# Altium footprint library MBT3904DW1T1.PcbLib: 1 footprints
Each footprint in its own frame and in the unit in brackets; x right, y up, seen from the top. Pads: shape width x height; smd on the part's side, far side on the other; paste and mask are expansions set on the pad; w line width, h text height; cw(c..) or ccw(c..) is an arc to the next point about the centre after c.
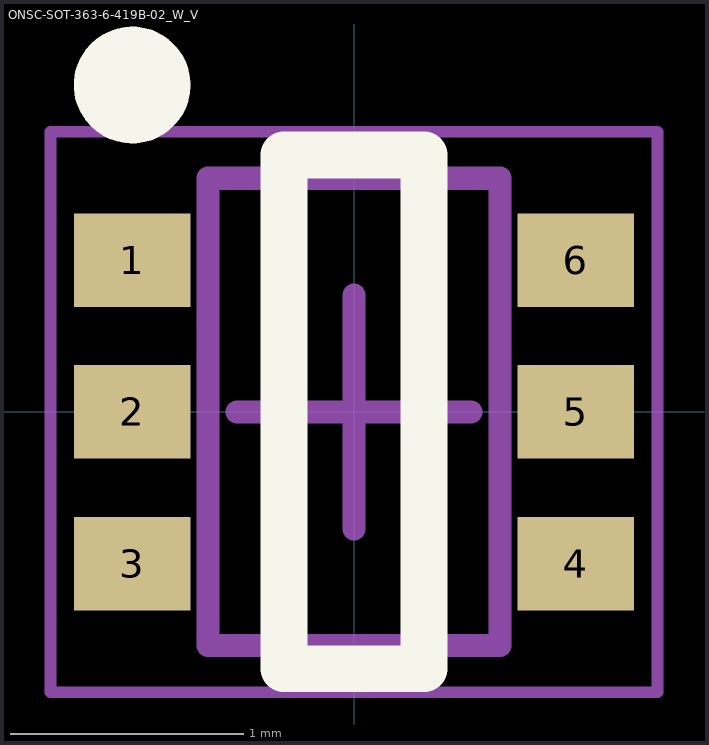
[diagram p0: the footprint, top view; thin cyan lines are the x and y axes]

## ONSC-SOT-363-6-419B-02_W_V [mm] "SOT23, 6-Leads, Body 2x1.25mm, Pitch 0.65mm"
height 1.1
pads (6):
  rect 0.5x0.4 smd: 1(-0.95,0.65) 2(-0.95,0) 3(-0.95,-0.65) 4(0.95,-0.65) 5(0.95,0) 6(0.95,0.65)
Top Overlay:
  circle w0.25: c-0.95,1.4 r0.125
  lines w0.2: -0.3,-1.1 -0.3,1.1 0.3,1.1 0.3,-1.1 -0.3,-1.1
Mechanical 13:
  lines w0.1: -0.625,-1 0.625,-1 0.625,1 -0.625,1 -0.625,-1
Mechanical 15:
  lines w0.05: -1.3,-1.2 1.3,-1.2 1.3,1.2 -1.3,1.2 -1.3,-1.2
  lines w0.1: -0.5,0 0.5,0 ; 0,-0.5 0,0.5
3D body: height 1.1, standoff 0, extent -0.625,-1 0.625,1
